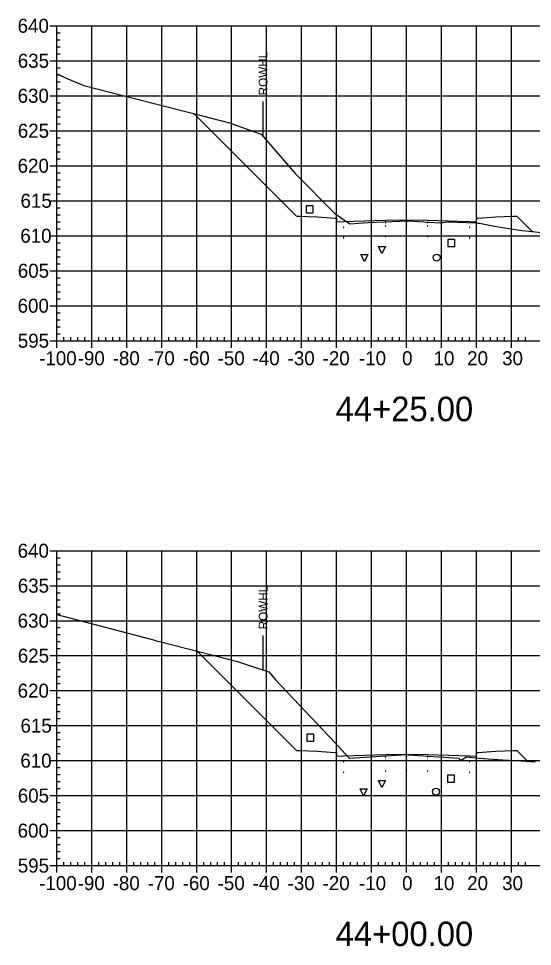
# Model space of a CAD drawing. Extents: x 708103 to 717568, y 374476 to 378707.
# Drawn here: x 711966.1 to 712112.9, y 377081.5 to 377346.7 of the extents above; entities that cross this region are included whole.
import ezdxf

# ---------------------------------------------------------------- set-up
doc = ezdxf.new("R2010")
doc.units = 0
for name, color, linetype in [('1', 7, 'Continuous'), ('10', 7, 'Continuous'), ('13', 7, 'Continuous'), ('14', 7, 'Continuous'), ('22', 7, 'Continuous'), ('4', 7, 'Continuous'), ('57', 7, 'Continuous'), ('Existing', 7, 'Continuous'), ('XS_Right_of_Way', 7, 'Continuous')]:
    doc.layers.add(name, color=color, linetype=linetype)

msp = doc.modelspace()

# ---------------------------------------------------------------- linework, layer by layer
for points in [[(712058.93, 377286.98), (712059.03, 377286.98), (712059.03, 377287.08), (712058.93, 377287.08)], [(712070.93, 377288.34), (712071.03, 377288.34), (712071.03, 377288.44), (712070.93, 377288.44)], [(712070.93, 377287.34), (712071.03, 377287.34), (712071.03, 377287.44), (712070.93, 377287.44)], [(712076.93, 377288.46), (712077.03, 377288.46), (712077.03, 377288.56), (712076.93, 377288.56)], [(712076.93, 377287.46), (712077.03, 377287.46), (712077.03, 377287.56), (712076.93, 377287.56)], [(712082.93, 377288.34), (712083.03, 377288.34), (712083.03, 377288.44), (712082.93, 377288.44)], [(712082.93, 377287.34), (712083.03, 377287.34), (712083.03, 377287.44), (712082.93, 377287.44)], [(712094.93, 377286.98), (712095.03, 377286.98), (712095.03, 377287.08), (712094.93, 377287.08)], [(712070.93, 377284.34), (712071.03, 377284.34), (712071.03, 377284.44), (712070.93, 377284.44)], [(712076.93, 377284.46), (712077.03, 377284.46), (712077.03, 377284.56), (712076.93, 377284.56)], [(712082.93, 377284.34), (712083.03, 377284.34), (712083.03, 377284.44), (712082.93, 377284.44)], [(712058.93, 377283.98), (712059.03, 377283.98), (712059.03, 377284.08), (712058.93, 377284.08)], [(712094.93, 377283.98), (712095.03, 377283.98), (712095.03, 377284.08), (712094.93, 377284.08)], [(712070.93, 377135.63), (712071.03, 377135.63), (712071.03, 377135.73), (712070.93, 377135.73)], [(712076.93, 377135.75), (712077.03, 377135.75), (712077.03, 377135.85), (712076.93, 377135.85)], [(712082.93, 377135.63), (712083.03, 377135.63), (712083.03, 377135.73), (712082.93, 377135.73)], [(712058.93, 377134.27), (712059.03, 377134.27), (712059.03, 377134.37), (712058.93, 377134.37)], [(712070.93, 377134.63), (712071.03, 377134.63), (712071.03, 377134.73), (712070.93, 377134.73)], [(712076.93, 377134.75), (712077.03, 377134.75), (712077.03, 377134.85), (712076.93, 377134.85)], [(712082.93, 377134.63), (712083.03, 377134.63), (712083.03, 377134.73), (712082.93, 377134.73)], [(712094.93, 377134.27), (712095.03, 377134.27), (712095.03, 377134.37), (712094.93, 377134.37)], [(712058.93, 377131.27), (712059.03, 377131.27), (712059.03, 377131.37), (712058.93, 377131.37)], [(712070.93, 377131.63), (712071.03, 377131.63), (712071.03, 377131.73), (712070.93, 377131.73)], [(712076.93, 377131.75), (712077.03, 377131.75), (712077.03, 377131.85), (712076.93, 377131.85)], [(712082.93, 377131.63), (712083.03, 377131.63), (712083.03, 377131.73), (712082.93, 377131.73)], [(712094.93, 377131.27), (712095.03, 377131.27), (712095.03, 377131.37), (712094.93, 377131.37)]]:
    msp.add_lwpolyline(points, close=True)
at = {"layer": '1'}
for points in [[(712069.92, 377279.56), (712068.92, 377281.56), (712070.92, 377281.56)], [(712064.93, 377277.31), (712063.93, 377279.31), (712065.93, 377279.31)], [(712069.93, 377126.92), (712068.93, 377128.92), (712070.93, 377128.92)], [(712064.69, 377124.61), (712063.69, 377126.61), (712065.69, 377126.61)]]:
    msp.add_lwpolyline(points, close=True, dxfattribs=at)
at = {"layer": '10'}
for points in [[(712048.3, 377291.22), (712050.3, 377291.22), (712050.3, 377293.22), (712048.3, 377293.22)], [(712048.45, 377140.22), (712050.45, 377140.22), (712050.45, 377142.22), (712048.45, 377142.22)]]:
    msp.add_lwpolyline(points, close=True, dxfattribs=at)
at = {"layer": '13'}
for centre in [(712085.6, 377278.38), (712085.41, 377125.76)]:
    msp.add_circle(centre, 1, dxfattribs=at)
at = {"layer": '14'}
for points in [[(712016.23, 377319.51), (712016.23, 377319.56), (712016.23, 377319.51), (712016.18, 377319.51), (712016.23, 377319.51), (712016.23, 377319.46), (712016.23, 377319.51), (712016.28, 377319.51)], [(712058.98, 377288.69), (712058.98, 377288.74), (712058.98, 377288.69), (712058.93, 377288.69), (712058.98, 377288.69), (712058.98, 377288.64), (712058.98, 377288.69), (712059.03, 377288.69)], [(712076.98, 377289.17), (712076.98, 377289.22), (712076.98, 377289.17), (712076.93, 377289.17), (712076.98, 377289.17), (712076.98, 377289.12), (712076.98, 377289.17), (712077.03, 377289.17)], [(712094.98, 377288.69), (712094.98, 377288.74), (712094.98, 377288.69), (712094.93, 377288.69), (712094.98, 377288.69), (712094.98, 377288.64), (712094.98, 377288.69), (712095.03, 377288.69)], [(712112.86, 377285.88), (712112.86, 377285.93), (712112.86, 377285.88), (712112.81, 377285.88), (712112.86, 377285.88), (712112.86, 377285.83), (712112.86, 377285.88), (712112.91, 377285.88)], [(712017.14, 377165.89), (712017.14, 377165.94), (712017.14, 377165.89), (712017.09, 377165.89), (712017.14, 377165.89), (712017.14, 377165.84), (712017.14, 377165.89), (712017.19, 377165.89)], [(712058.98, 377135.99), (712058.98, 377136.04), (712058.98, 377135.99), (712058.93, 377135.99), (712058.98, 377135.99), (712058.98, 377135.94), (712058.98, 377135.99), (712059.03, 377135.99)], [(712076.98, 377136.47), (712076.98, 377136.52), (712076.98, 377136.47), (712076.93, 377136.47), (712076.98, 377136.47), (712076.98, 377136.42), (712076.98, 377136.47), (712077.03, 377136.47)], [(712094.98, 377135.99), (712094.98, 377136.04), (712094.98, 377135.99), (712094.93, 377135.99), (712094.98, 377135.99), (712094.98, 377135.94), (712094.98, 377135.99), (712095.03, 377135.99)], [(712111.62, 377134.41), (712111.62, 377134.46), (712111.62, 377134.41), (712111.57, 377134.41), (712111.62, 377134.41), (712111.62, 377134.36), (712111.62, 377134.41), (712111.67, 377134.41)]]:
    msp.add_lwpolyline(points, dxfattribs=at)
at = {"layer": '22'}
for points in [[(712016.23, 377319.51), (712045.48, 377290.25), (712046.48, 377290.21), (712051.48, 377290.01), (712056.48, 377289.61), (712056.9, 377289.61), (712056.98, 377288.61), (712058.98, 377288.69), (712070.98, 377289.05), (712076.98, 377289.17), (712082.98, 377289.05), (712094.98, 377288.69), (712096.98, 377288.61), (712097.07, 377289.61), (712097.48, 377289.61), (712102.48, 377290.01), (712107.48, 377290.21), (712108.48, 377290.25), (712112.86, 377285.88)], [(712017.14, 377165.89), (712045.48, 377137.55), (712046.48, 377137.51), (712051.48, 377137.31), (712056.48, 377136.91), (712056.9, 377136.91), (712056.98, 377135.91), (712058.98, 377135.99), (712070.98, 377136.35), (712076.98, 377136.47), (712082.98, 377136.35), (712094.98, 377135.99), (712096.98, 377135.91), (712097.07, 377136.91), (712097.48, 377136.91), (712102.48, 377137.31), (712107.48, 377137.51), (712108.48, 377137.55), (712111.62, 377134.41)]]:
    msp.add_lwpolyline(points, dxfattribs=at)
at = {"layer": '4'}
for points in [[(712088.73, 377281.59), (712090.73, 377281.59), (712090.73, 377283.59), (712088.73, 377283.59)], [(712088.69, 377128.46), (712090.69, 377128.46), (712090.69, 377130.46), (712088.69, 377130.46)]]:
    msp.add_lwpolyline(points, close=True, dxfattribs=at)
at = {"layer": '57'}
for p, q in [((711974.98, 377344.63), (711976.98, 377344.63)), ((711976.98, 377344.63), (712176.98, 377344.63)), ((711976.98, 377254.63), (711976.98, 377344.63)), ((711976.98, 377254.63), (711976.98, 377344.63)), ((711976.98, 377342.63), (711977.98, 377342.63)), ((711986.98, 377254.63), (711986.98, 377344.63)), ((711996.98, 377254.63), (711996.98, 377344.63)), ((712006.98, 377254.63), (712006.98, 377344.63)), ((712016.98, 377254.63), (712016.98, 377344.63)), ((712026.98, 377254.63), (712026.98, 377344.63)), ((712036.98, 377254.63), (712036.98, 377344.63)), ((712046.98, 377254.63), (712046.98, 377344.63)), ((712056.98, 377254.63), (712056.98, 377344.63)), ((712066.98, 377254.63), (712066.98, 377344.63)), ((712076.98, 377254.63), (712076.98, 377344.63)), ((712086.98, 377254.63), (712086.98, 377344.63)), ((712096.98, 377254.63), (712096.98, 377344.63)), ((712106.98, 377254.63), (712106.98, 377344.63)), ((711976.98, 377340.63), (711977.98, 377340.63)), ((711976.98, 377338.63), (711977.98, 377338.63)), ((711974.98, 377334.63), (711976.98, 377334.63)), ((711976.98, 377336.63), (711977.98, 377336.63)), ((711976.98, 377334.63), (712176.98, 377334.63)), ((711976.98, 377332.63), (711977.98, 377332.63)), ((711976.98, 377330.63), (711977.98, 377330.63)), ((711976.98, 377328.63), (711977.98, 377328.63)), ((711976.98, 377326.63), (711977.98, 377326.63)), ((711974.98, 377324.63), (711976.98, 377324.63)), ((711976.98, 377324.63), (712176.98, 377324.63)), ((711976.98, 377322.63), (711977.98, 377322.63)), ((711976.98, 377320.63), (711977.98, 377320.63)), ((711976.98, 377318.63), (711977.98, 377318.63)), ((711976.98, 377316.63), (711977.98, 377316.63)), ((711974.98, 377314.63), (711976.98, 377314.63)), ((711976.98, 377314.63), (712176.98, 377314.63)), ((711976.98, 377312.63), (711977.98, 377312.63)), ((711976.98, 377310.63), (711977.98, 377310.63)), ((711976.98, 377308.63), (711977.98, 377308.63)), ((711976.98, 377306.63), (711977.98, 377306.63)), ((711974.98, 377304.63), (711976.98, 377304.63)), ((711976.98, 377304.63), (712176.98, 377304.63)), ((711976.98, 377302.63), (711977.98, 377302.63)), ((711976.98, 377300.63), (711977.98, 377300.63)), ((711976.98, 377298.63), (711977.98, 377298.63)), ((711976.98, 377296.63), (711977.98, 377296.63)), ((711974.98, 377294.63), (711976.98, 377294.63)), ((711976.98, 377294.63), (712176.98, 377294.63)), ((711976.98, 377292.63), (711977.98, 377292.63)), ((711976.98, 377290.63), (711977.98, 377290.63)), ((711976.98, 377288.63), (711977.98, 377288.63)), ((711974.98, 377284.63), (711976.98, 377284.63)), ((711976.98, 377286.63), (711977.98, 377286.63)), ((711976.98, 377284.63), (712176.98, 377284.63)), ((711976.98, 377282.63), (711977.98, 377282.63)), ((711976.98, 377280.63), (711977.98, 377280.63)), ((711976.98, 377278.63), (711977.98, 377278.63)), ((711976.98, 377276.63), (711977.98, 377276.63)), ((711974.98, 377274.63), (711976.98, 377274.63)), ((711976.98, 377274.63), (712176.98, 377274.63)), ((711976.98, 377272.63), (711977.98, 377272.63)), ((711976.98, 377270.63), (711977.98, 377270.63)), ((711976.98, 377268.63), (711977.98, 377268.63)), ((711976.98, 377266.63), (711977.98, 377266.63)), ((711974.98, 377264.63), (711976.98, 377264.63)), ((711976.98, 377264.63), (712176.98, 377264.63)), ((711976.98, 377262.63), (711977.98, 377262.63)), ((711976.98, 377260.63), (711977.98, 377260.63)), ((711976.98, 377258.63), (711977.98, 377258.63)), ((711976.98, 377256.63), (711977.98, 377256.63)), ((711978.98, 377254.63), (711978.98, 377255.63)), ((711980.98, 377254.63), (711980.98, 377255.63)), ((711982.98, 377254.63), (711982.98, 377255.63)), ((711984.98, 377254.63), (711984.98, 377255.63)), ((711988.98, 377254.63), (711988.98, 377255.63)), ((711990.98, 377254.63), (711990.98, 377255.63)), ((711992.98, 377254.63), (711992.98, 377255.63)), ((711994.98, 377254.63), (711994.98, 377255.63)), ((711998.98, 377254.63), (711998.98, 377255.63)), ((712000.98, 377254.63), (712000.98, 377255.63)), ((712002.98, 377254.63), (712002.98, 377255.63)), ((712004.98, 377254.63), (712004.98, 377255.63)), ((712008.98, 377254.63), (712008.98, 377255.63)), ((712010.98, 377254.63), (712010.98, 377255.63)), ((712012.98, 377254.63), (712012.98, 377255.63)), ((712014.98, 377254.63), (712014.98, 377255.63)), ((712018.98, 377254.63), (712018.98, 377255.63)), ((712020.98, 377254.63), (712020.98, 377255.63)), ((712022.98, 377254.63), (712022.98, 377255.63)), ((712024.98, 377254.63), (712024.98, 377255.63)), ((712028.98, 377254.63), (712028.98, 377255.63)), ((712030.98, 377254.63), (712030.98, 377255.63)), ((712032.98, 377254.63), (712032.98, 377255.63)), ((712034.98, 377254.63), (712034.98, 377255.63)), ((712038.98, 377254.63), (712038.98, 377255.63)), ((712040.98, 377254.63), (712040.98, 377255.63)), ((712042.98, 377254.63), (712042.98, 377255.63)), ((712044.98, 377254.63), (712044.98, 377255.63)), ((712048.98, 377254.63), (712048.98, 377255.63)), ((712050.98, 377254.63), (712050.98, 377255.63)), ((712052.98, 377254.63), (712052.98, 377255.63)), ((712054.98, 377254.63), (712054.98, 377255.63)), ((712058.98, 377254.63), (712058.98, 377255.63)), ((712060.98, 377254.63), (712060.98, 377255.63)), ((712062.98, 377254.63), (712062.98, 377255.63)), ((712064.98, 377254.63), (712064.98, 377255.63)), ((712068.98, 377254.63), (712068.98, 377255.63)), ((712070.98, 377254.63), (712070.98, 377255.63)), ((712072.98, 377254.63), (712072.98, 377255.63)), ((712074.98, 377254.63), (712074.98, 377255.63)), ((712078.98, 377254.63), (712078.98, 377255.63)), ((712080.98, 377254.63), (712080.98, 377255.63)), ((712082.98, 377254.63), (712082.98, 377255.63)), ((712084.98, 377254.63), (712084.98, 377255.63)), ((712088.98, 377254.63), (712088.98, 377255.63)), ((712090.98, 377254.63), (712090.98, 377255.63)), ((712092.98, 377254.63), (712092.98, 377255.63)), ((712094.98, 377254.63), (712094.98, 377255.63)), ((712098.98, 377254.63), (712098.98, 377255.63)), ((712100.98, 377254.63), (712100.98, 377255.63)), ((712102.98, 377254.63), (712102.98, 377255.63)), ((712104.98, 377254.63), (712104.98, 377255.63)), ((712108.98, 377254.63), (712108.98, 377255.63)), ((712110.98, 377254.63), (712110.98, 377255.63)), ((711974.98, 377254.63), (711976.98, 377254.63)), ((711976.98, 377254.63), (712176.98, 377254.63)), ((711976.98, 377254.63), (712176.98, 377254.63)), ((711976.98, 377252.63), (711976.98, 377254.63)), ((711986.98, 377252.63), (711986.98, 377254.63)), ((711996.98, 377252.63), (711996.98, 377254.63)), ((712006.98, 377252.63), (712006.98, 377254.63)), ((712016.98, 377252.63), (712016.98, 377254.63)), ((712026.98, 377252.63), (712026.98, 377254.63)), ((712036.98, 377252.63), (712036.98, 377254.63)), ((712046.98, 377252.63), (712046.98, 377254.63)), ((712056.98, 377252.63), (712056.98, 377254.63)), ((712066.98, 377252.63), (712066.98, 377254.63)), ((712076.98, 377252.63), (712076.98, 377254.63)), ((712086.98, 377252.63), (712086.98, 377254.63)), ((712096.98, 377252.63), (712096.98, 377254.63)), ((712106.98, 377252.63), (712106.98, 377254.63)), ((711974.98, 377194.63), (711976.98, 377194.63)), ((711976.98, 377194.63), (712176.98, 377194.63)), ((711976.98, 377104.63), (711976.98, 377194.63)), ((711976.98, 377104.63), (711976.98, 377194.63)), ((711986.98, 377104.63), (711986.98, 377194.63)), ((711996.98, 377104.63), (711996.98, 377194.63)), ((712006.98, 377104.63), (712006.98, 377194.63)), ((712016.98, 377104.63), (712016.98, 377194.63)), ((712026.98, 377104.63), (712026.98, 377194.63)), ((712036.98, 377104.63), (712036.98, 377194.63)), ((712046.98, 377104.63), (712046.98, 377194.63)), ((712056.98, 377104.63), (712056.98, 377194.63)), ((712066.98, 377104.63), (712066.98, 377194.63)), ((712076.98, 377104.63), (712076.98, 377194.63)), ((712086.98, 377104.63), (712086.98, 377194.63)), ((712096.98, 377104.63), (712096.98, 377194.63)), ((712106.98, 377104.63), (712106.98, 377194.63)), ((711976.98, 377192.63), (711977.98, 377192.63)), ((711976.98, 377190.63), (711977.98, 377190.63)), ((711976.98, 377188.63), (711977.98, 377188.63)), ((711976.98, 377186.63), (711977.98, 377186.63)), ((711974.98, 377184.63), (711976.98, 377184.63)), ((711976.98, 377184.63), (712176.98, 377184.63)), ((711976.98, 377182.63), (711977.98, 377182.63)), ((711976.98, 377180.63), (711977.98, 377180.63)), ((711976.98, 377178.63), (711977.98, 377178.63)), ((711976.98, 377176.63), (711977.98, 377176.63)), ((711974.98, 377174.63), (711976.98, 377174.63)), ((711976.98, 377174.63), (712176.98, 377174.63)), ((711976.98, 377172.63), (711977.98, 377172.63)), ((711976.98, 377170.63), (711977.98, 377170.63)), ((711976.98, 377168.63), (711977.98, 377168.63)), ((711976.98, 377166.63), (711977.98, 377166.63)), ((711974.98, 377164.63), (711976.98, 377164.63)), ((711976.98, 377164.63), (712176.98, 377164.63)), ((711976.98, 377162.63), (711977.98, 377162.63)), ((711976.98, 377160.63), (711977.98, 377160.63)), ((711976.98, 377158.63), (711977.98, 377158.63)), ((711974.98, 377154.63), (711976.98, 377154.63)), ((711976.98, 377156.63), (711977.98, 377156.63)), ((711976.98, 377154.63), (712176.98, 377154.63)), ((711976.98, 377152.63), (711977.98, 377152.63)), ((711976.98, 377150.63), (711977.98, 377150.63)), ((711976.98, 377148.63), (711977.98, 377148.63)), ((711976.98, 377146.63), (711977.98, 377146.63)), ((711974.98, 377144.63), (711976.98, 377144.63)), ((711976.98, 377144.63), (712176.98, 377144.63)), ((711976.98, 377142.63), (711977.98, 377142.63)), ((711976.98, 377140.63), (711977.98, 377140.63)), ((711976.98, 377138.63), (711977.98, 377138.63)), ((711976.98, 377136.63), (711977.98, 377136.63)), ((711974.98, 377134.63), (711976.98, 377134.63)), ((711976.98, 377134.63), (712176.98, 377134.63)), ((711976.98, 377132.63), (711977.98, 377132.63)), ((711976.98, 377130.63), (711977.98, 377130.63)), ((711976.98, 377128.63), (711977.98, 377128.63)), ((711976.98, 377126.63), (711977.98, 377126.63)), ((711974.98, 377124.63), (711976.98, 377124.63)), ((711976.98, 377124.63), (712176.98, 377124.63)), ((711976.98, 377122.63), (711977.98, 377122.63)), ((711976.98, 377120.63), (711977.98, 377120.63)), ((711976.98, 377118.63), (711977.98, 377118.63)), ((711974.98, 377114.63), (711976.98, 377114.63)), ((711976.98, 377116.63), (711977.98, 377116.63)), ((711976.98, 377114.63), (712176.98, 377114.63)), ((711976.98, 377112.63), (711977.98, 377112.63)), ((711976.98, 377110.63), (711977.98, 377110.63)), ((711976.98, 377108.63), (711977.98, 377108.63)), ((711976.98, 377106.63), (711977.98, 377106.63)), ((711974.98, 377104.63), (711976.98, 377104.63)), ((711976.98, 377104.63), (712176.98, 377104.63)), ((711976.98, 377104.63), (712176.98, 377104.63)), ((711976.98, 377102.63), (711976.98, 377104.63)), ((711978.98, 377104.63), (711978.98, 377105.63)), ((711980.98, 377104.63), (711980.98, 377105.63)), ((711982.98, 377104.63), (711982.98, 377105.63)), ((711984.98, 377104.63), (711984.98, 377105.63)), ((711986.98, 377102.63), (711986.98, 377104.63)), ((711988.98, 377104.63), (711988.98, 377105.63)), ((711990.98, 377104.63), (711990.98, 377105.63)), ((711992.98, 377104.63), (711992.98, 377105.63)), ((711994.98, 377104.63), (711994.98, 377105.63)), ((711996.98, 377102.63), (711996.98, 377104.63)), ((711998.98, 377104.63), (711998.98, 377105.63)), ((712000.98, 377104.63), (712000.98, 377105.63)), ((712002.98, 377104.63), (712002.98, 377105.63)), ((712004.98, 377104.63), (712004.98, 377105.63)), ((712006.98, 377102.63), (712006.98, 377104.63)), ((712008.98, 377104.63), (712008.98, 377105.63)), ((712010.98, 377104.63), (712010.98, 377105.63)), ((712012.98, 377104.63), (712012.98, 377105.63)), ((712014.98, 377104.63), (712014.98, 377105.63)), ((712016.98, 377102.63), (712016.98, 377104.63)), ((712018.98, 377104.63), (712018.98, 377105.63)), ((712020.98, 377104.63), (712020.98, 377105.63)), ((712022.98, 377104.63), (712022.98, 377105.63)), ((712024.98, 377104.63), (712024.98, 377105.63)), ((712026.98, 377102.63), (712026.98, 377104.63)), ((712028.98, 377104.63), (712028.98, 377105.63)), ((712030.98, 377104.63), (712030.98, 377105.63)), ((712032.98, 377104.63), (712032.98, 377105.63)), ((712034.98, 377104.63), (712034.98, 377105.63)), ((712036.98, 377102.63), (712036.98, 377104.63)), ((712038.98, 377104.63), (712038.98, 377105.63)), ((712040.98, 377104.63), (712040.98, 377105.63)), ((712042.98, 377104.63), (712042.98, 377105.63)), ((712044.98, 377104.63), (712044.98, 377105.63)), ((712046.98, 377102.63), (712046.98, 377104.63)), ((712048.98, 377104.63), (712048.98, 377105.63)), ((712050.98, 377104.63), (712050.98, 377105.63)), ((712052.98, 377104.63), (712052.98, 377105.63)), ((712054.98, 377104.63), (712054.98, 377105.63)), ((712056.98, 377102.63), (712056.98, 377104.63)), ((712058.98, 377104.63), (712058.98, 377105.63)), ((712060.98, 377104.63), (712060.98, 377105.63)), ((712062.98, 377104.63), (712062.98, 377105.63)), ((712064.98, 377104.63), (712064.98, 377105.63)), ((712066.98, 377102.63), (712066.98, 377104.63)), ((712068.98, 377104.63), (712068.98, 377105.63)), ((712070.98, 377104.63), (712070.98, 377105.63)), ((712072.98, 377104.63), (712072.98, 377105.63)), ((712074.98, 377104.63), (712074.98, 377105.63)), ((712076.98, 377102.63), (712076.98, 377104.63)), ((712078.98, 377104.63), (712078.98, 377105.63)), ((712080.98, 377104.63), (712080.98, 377105.63)), ((712082.98, 377104.63), (712082.98, 377105.63)), ((712084.98, 377104.63), (712084.98, 377105.63)), ((712086.98, 377102.63), (712086.98, 377104.63)), ((712088.98, 377104.63), (712088.98, 377105.63)), ((712090.98, 377104.63), (712090.98, 377105.63)), ((712092.98, 377104.63), (712092.98, 377105.63)), ((712094.98, 377104.63), (712094.98, 377105.63)), ((712096.98, 377102.63), (712096.98, 377104.63)), ((712098.98, 377104.63), (712098.98, 377105.63)), ((712100.98, 377104.63), (712100.98, 377105.63)), ((712102.98, 377104.63), (712102.98, 377105.63)), ((712104.98, 377104.63), (712104.98, 377105.63)), ((712106.98, 377102.63), (712106.98, 377104.63)), ((712108.98, 377104.63), (712108.98, 377105.63)), ((712110.98, 377104.63), (712110.98, 377105.63))]:
    msp.add_line(p, q, dxfattribs=at)
at = {"layer": 'Existing'}
for points in [[(711976.98, 377330.9), (711980.19, 377329.47), (711984.75, 377327.61), (712000.32, 377323.53), (712018.25, 377319), (712026.39, 377316.9), (712033.22, 377314.4), (712035.43, 377313.68), (712045.1, 377302.44), (712056.51, 377290.99), (712060.79, 377288.07), (712065.99, 377288.38), (712077.2, 377288.91), (712086.63, 377288.31), (712088.7, 377288.64), (712094.06, 377288.37), (712097.12, 377288.3), (712097.45, 377288.27), (712097.84, 377288.19), (712102.12, 377287.36), (712109.28, 377286.25), (712115.52, 377285.6)], [(711976.98, 377176.35), (712004.6, 377169.12), (712005.44, 377168.9), (712005.52, 377168.88), (712006.72, 377168.57), (712028.69, 377162.92), (712029.18, 377162.74), (712032.61, 377161.62), (712037.62, 377159.97), (712039.59, 377157.6), (712056.5, 377139.8), (712060.4, 377135.52), (712060.62, 377135.37), (712076.98, 377136.34), (712077.14, 377136.35), (712077.48, 377136.32), (712091.9, 377135.3), (712092.01, 377135.25), (712092.24, 377134.81), (712093.04, 377135.07), (712094, 377135.72), (712097.51, 377135.38), (712104.51, 377134.82), (712109.7, 377134.54), (712113.77, 377134.26)]]:
    msp.add_lwpolyline(points, dxfattribs=at)
at = {"layer": 'XS_Right_of_Way'}
for p, q in [((712035.9, 377323), (712035.9, 377313)), ((712035.92, 377170.39), (712035.92, 377160.39))]:
    msp.add_line(p, q, dxfattribs=at)

# ---------------------------------------------------------------- texts
at = {"layer": '1'}
for s, p in [('44+25.00', (712056.71, 377231.63)), ('44+00.00', (712056.71, 377081.63))]:
    msp.add_text(s, height=7, dxfattribs=at).set_placement(p)
at = {"layer": '14'}
for p in [(712046.45, 377290.16), (712046.45, 377289.5), (712107.45, 377290.16), (712107.45, 377289.5), (712051.45, 377289.3), (712102.45, 377289.3), (712046.45, 377137.46), (712046.45, 377136.79), (712051.45, 377136.59), (712102.45, 377136.59), (712107.45, 377137.46), (712107.45, 377136.79)]:
    msp.add_text('+', height=0.1, dxfattribs=at).set_placement(p)
at = {"layer": '57'}
for s, p in [('640', (711965.81, 377342.63)), ('635', (711965.86, 377332.63)), ('630', (711965.81, 377322.63)), ('625', (711965.86, 377312.63)), ('620', (711965.81, 377302.63)), ('615', (711966.63, 377292.63)), ('610', (711966.58, 377282.63)), ('605', (711965.86, 377272.63)), ('600', (711965.81, 377262.63)), ('595', (711965.86, 377252.63)), ('-100', (711971.97, 377247.63)), ('-90', (711982.98, 377247.63)), ('-80', (711992.98, 377247.63)), ('-70', (712002.98, 377247.63)), ('-60', (712012.98, 377247.63)), ('-50', (712022.98, 377247.63)), ('-40', (712032.98, 377247.63)), ('-30', (712042.98, 377247.63)), ('-20', (712052.98, 377247.63)), ('-10', (712063.37, 377247.63)), ('0', (712075.69, 377247.63)), ('10', (712084.68, 377247.63)), ('20', (712094.29, 377247.63)), ('30', (712104.29, 377247.63)), ('640', (711965.81, 377192.63)), ('635', (711965.86, 377182.63)), ('630', (711965.81, 377172.63)), ('625', (711965.86, 377162.63)), ('620', (711965.81, 377152.63)), ('615', (711966.63, 377142.63)), ('610', (711966.58, 377132.63)), ('605', (711965.86, 377122.63)), ('600', (711965.81, 377112.63)), ('595', (711965.86, 377102.63)), ('-100', (711971.97, 377097.63)), ('-90', (711982.98, 377097.63)), ('-80', (711992.98, 377097.63)), ('-70', (712002.98, 377097.63)), ('-60', (712012.98, 377097.63)), ('-50', (712022.98, 377097.63)), ('-40', (712032.98, 377097.63)), ('-30', (712042.98, 377097.63)), ('-20', (712052.98, 377097.63)), ('-10', (712063.37, 377097.63)), ('0', (712075.69, 377097.63)), ('10', (712084.68, 377097.63)), ('20', (712094.29, 377097.63)), ('30', (712104.29, 377097.63))]:
    msp.add_text(s, height=4, dxfattribs=at).set_placement(p)
at = {"layer": 'XS_Right_of_Way'}
for p in [(712037.22, 377324.76), (712037.24, 377172.15)]:
    msp.add_text('ROWHL', height=2.5, rotation=90, dxfattribs=at).set_placement(p)

doc.saveas('drawing.dxf')
